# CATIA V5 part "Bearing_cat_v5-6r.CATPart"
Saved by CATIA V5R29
Part number: Bearing
Bounding box of the stored display mesh (mm): x -10 to 10, y -17.5 to 17.5, z -17.322 to 17.322
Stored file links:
  C:\Users\CADCIM 00\Desktop\New folder (2)\c16\New folder\Cam Follower mechanism\Bearing_cat_v5-6r.CATPart
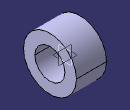
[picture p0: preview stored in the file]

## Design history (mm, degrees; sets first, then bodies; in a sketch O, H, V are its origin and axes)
Body1 (main body)
  Sketch1 on yz-plane, origin (0, 0, 0), H (0, 1, 0), V (0, 0, 1)
    circle A1 centre (0, 0) radius 10
    circle A2 centre (0, 0) radius 17.5
    radius A1 = 10
    radius A2 = 17.5
  Pad1: profile Sketch1, direction (1, 0, 0), length 10, mirrored extent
